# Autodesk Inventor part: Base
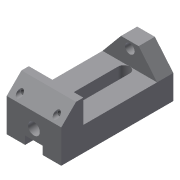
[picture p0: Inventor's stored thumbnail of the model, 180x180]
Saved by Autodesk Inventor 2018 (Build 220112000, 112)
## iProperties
Shininess: 77.0
Length Units: 11269
Angle Units: 11279
Time Units: 11290
Mass Units: 11283
Length Display Precision: 3
Angle Display Precision: 2
Created: 2002-02
Part Number: Base
Document SubType Name: Modeling
Designer: ***
Density: 1 g/cm^3
Material: Generic
Appearance: Default
Density: 0.0
Volumn: 0.0
Area: 0.0
PropertySet Name: Model Information
Control State: 0
Master: False
Checked Out: False
Author: ***
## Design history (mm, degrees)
sketch "Sketch2"
  geometry: L1 (-63.961, -4.254)-(-63.961, -37.254); L2 (-63.961, -37.254)-(88.039, -37.254); L3 (88.039, -37.254)-(88.039, 7.746); L4 (88.039, 7.746)-(68.039, 27.746); L5 (68.039, 27.746)-(58.039, 27.746); L6 (58.039, 27.746)-(58.039, -4.254); L7 (58.039, -4.254)-(-63.961, -4.254)
  constraints: 14 end point, 4 parallel, 1 perpendicular, 1 vertical
  dimensions: "d7" = 10 distance of L4.end L5.end; "d8" = 135 deg angle of L3 L4; "d9" = 33 distance of L1.start L1.end; "d10" = 152 distance of L1.end L2.end; "d11" = 65 distance between parallel lines of L5 L2; "d21" = 30 distance between parallel lines of L3 L6
extrude "Extrusion1" new body sketch "Sketch2" stored distance "d13" = 74; taper "d14" = 0 deg
sketch "Sketch3"
  geometry: L1 (0, 74)-(0, 0) reference; L2 (0, 0)-(-30, 25); L3 (-30, 25)-(-30, 49); L4 (-30, 49)-(0, 74); C1 r 6.5 at (-21, 37)
  constraints: 6 end point, 1 centre point, 1 equal length, 1 parallel
  dimensions: "d15" = 24 distance of L2.end L3.end; "d16" = 30 distance between parallel lines of L3 L1; "d17" = 13 diameter of C1; "d18" = 9 distance from line of L3 C1.centre
extrude "Extrusion2" join sketch "Sketch3" distance "d19" = 22; taper "d20" = 0 deg
sketch "Sketch4"
  geometry: L1 (0, 0)-(0, 74) reference; L2 (0, 0)-(45, 0) reference; C1 r 8 at (25, 37)
  constraints: 1 centre point
  dimensions: "d22" = 16 diameter of C1; "d23" = 25 distance from line of L1 C1.centre; "d24" = 37 distance from line of L2 C1.centre
extrude "Extrusion3" cut sketch "Sketch4" distance "d25" = 13; taper "d26" = 0 deg
sketch "Sketch5"
  geometry: L1 (45, 74)-(0, 74) reference; L2 (65, 0)-(65, 74) reference; 1 further point
  dimensions: "d27" = 12 distance from line of point (51, 62) L1; "d28" = 14 distance from line of L2 point (51, 62)
hole "Hole1" sketch "Sketch5" at (51, 62) diameter "d29" = 4.917; stored, may be unused: countersink angle "d33" = 82 deg, drill point angle "d35" = 0 deg; dims "d30" = 12, "d31" = 8, "d32" = 10, "d34" = 45
mirror "Mirror1"
sketch "Sketch6"
  geometry: L1 (100, 0)-(100, 74) reference; L2 (100, 74)-(0, 74) reference; L3 (14, 45)-(92, 45); L4 (92, 29)-(14, 29); A1 r 8 centre (92, 37) between (92, 29) and (92, 45); A2 r 8 centre (14, 37) between (14, 45) and (14, 29)
  constraints: 4 end point, 4 point on circle, 4 tangent, 2 centre point, 1 horizontal, 1 parallel
  dimensions: "d36" = 8 radius of A2; "d37" = 78 distance of L4.start L4.end; "d38" = 8 distance from line of L1 A1.centre; "d39" = 37 distance from line of L2 A2.centre
extrude "Extrusion4" cut sketch "Sketch6" extent not by distance; stored distance "d40" = 13; taper "d41" = 0 deg
sketch "Sketch7"
  geometry: L1 (45, 74)-(0, 74) reference; L2 (11, 49)-(0, 49); L3 (0, 49)-(0, 25); L4 (0, 25)-(11, 25); L5 (11, 25)-(11, 49); L6 (0, 0)-(45, 0) reference; L7 (0, 0)-(0, 74) reference
  constraints: 8 end point, 2 parallel, 1 collinear, 1 horizontal, 1 perpendicular
  dimensions: "d47" = 11 distance of L3.end L4.end; "d48" = 25 distance between parallel lines of L6 L4; "d49" = 24 distance of L2.end L3.end
extrude "Extrusion5" cut sketch "Sketch7" extent not by distance; stored distance "d45" = 13; taper "d46" = 0 deg
body "Solid1"
